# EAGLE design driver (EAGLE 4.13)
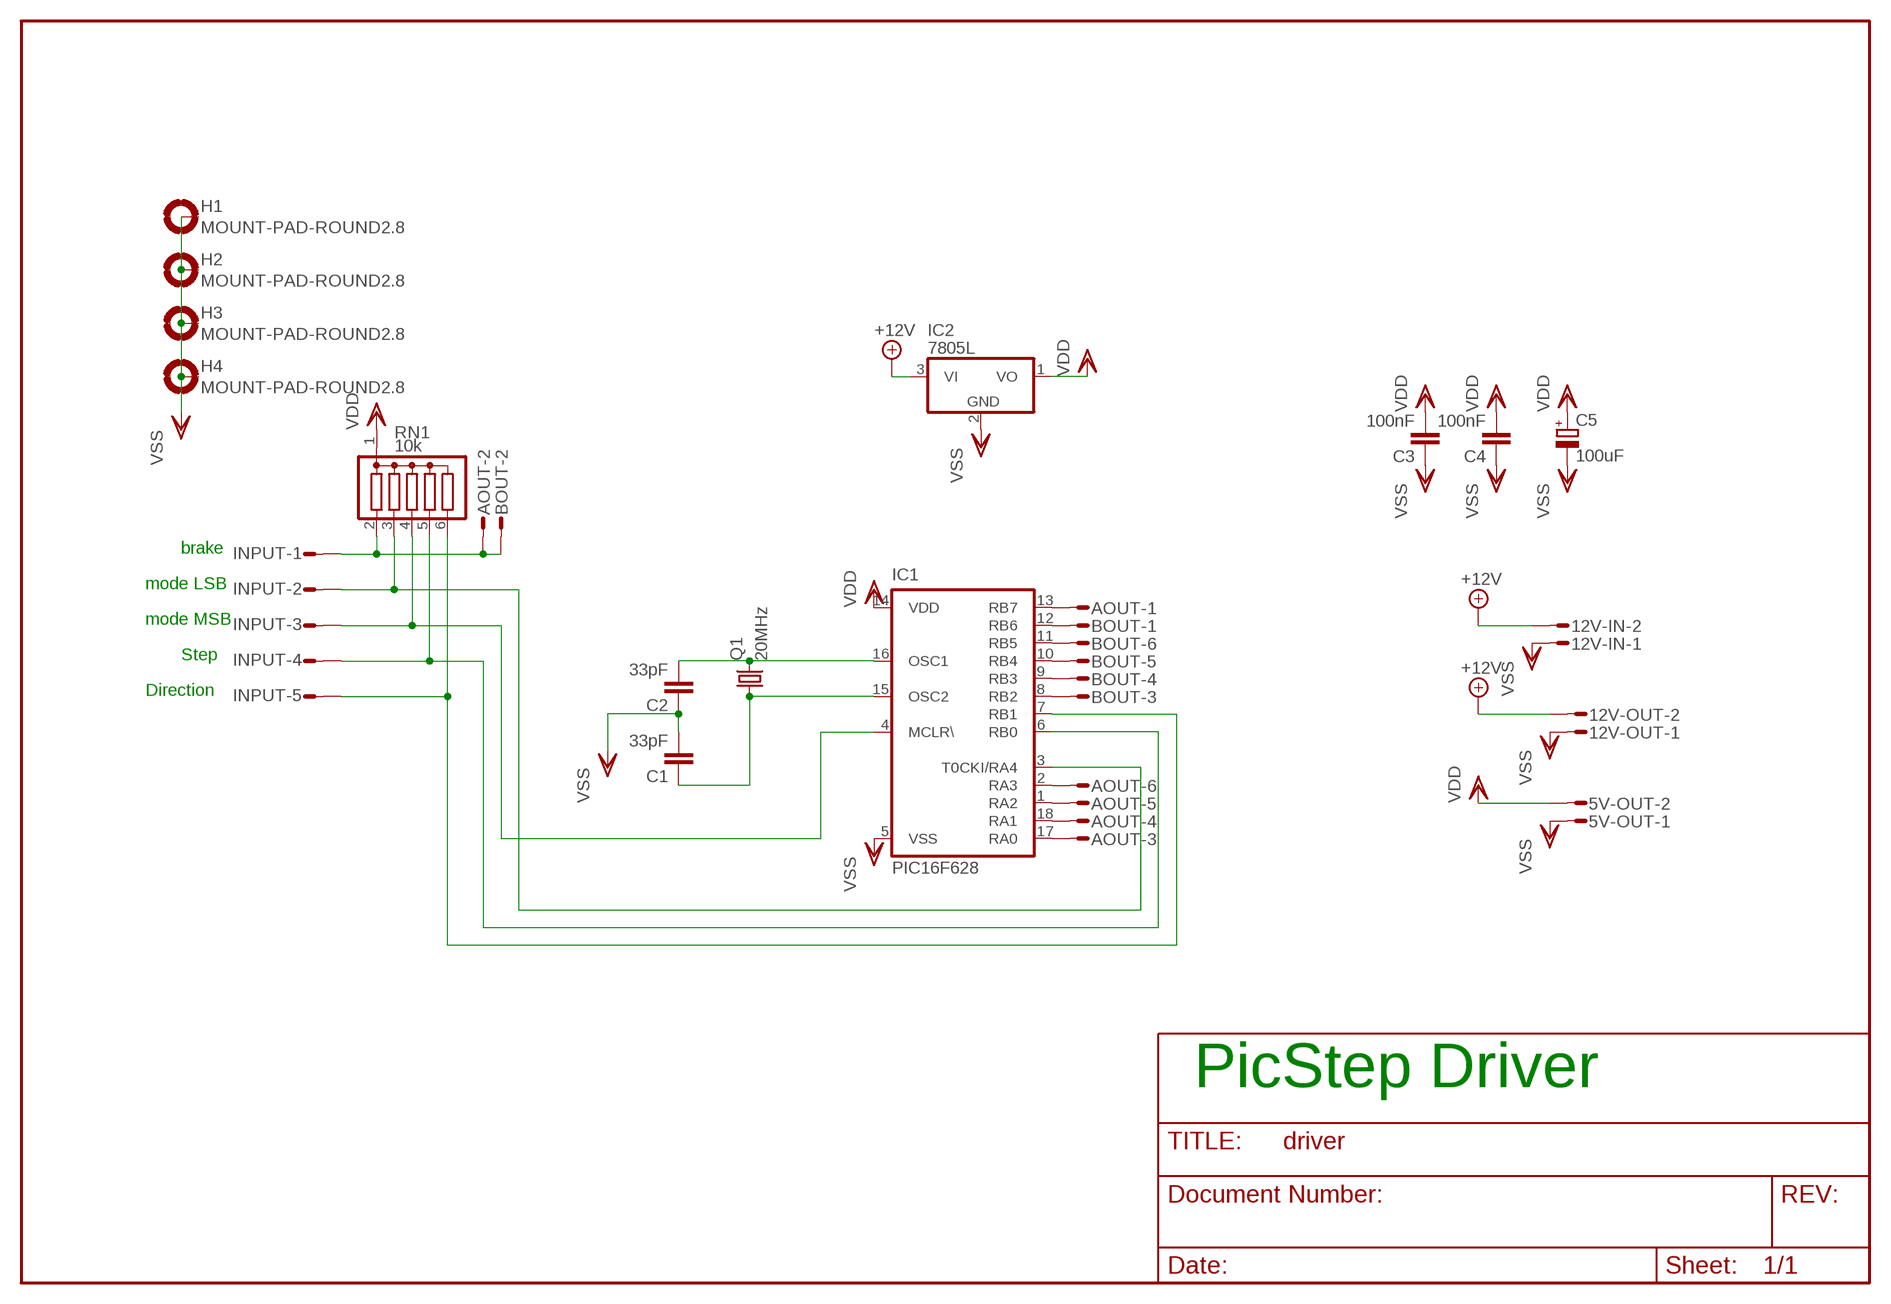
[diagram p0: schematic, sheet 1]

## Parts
5V-OUT  S02P  [S02P]
12V-IN  S02P  [S02P]
12V-OUT  S02P  [S02P]
AOUT  S06P  [S06P]
BOUT  S06P  [S06P]
C1  33pF  C-EU050-030X075  [C050-030X075]
C2  33pF  C-EU050-030X075  [C050-030X075]
C3  100nF  C-EU050-030X075  [C050-030X075]
C4  100nF  C-EU050-030X075  [C050-030X075]
C5  100uF  CPOL-EUE5-10.5  [E5-10,5]
H1  MOUNT-PAD-ROUND2.8  [2,8-PAD]
H2  MOUNT-PAD-ROUND2.8  [2,8-PAD]
H3  MOUNT-PAD-ROUND2.8  [2,8-PAD]
H4  MOUNT-PAD-ROUND2.8  [2,8-PAD]
IC1  PIC16F628  PIC16F84AP  [DIL18]
IC2  7805L  [TO92]
INPUT  S05P  [S05P]
Q1  20MHz  CRYTALHC49U-V  [HC49U-V]
RN1  10k  G05R  [SIL6]

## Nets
+12V: 12V-IN.2 12V-OUT.2 IC2.3(VI)
N$1: C2.2 IC1.16(OSC1) Q1.2
N$2: C1.1 IC1.15(OSC2) Q1.1
N$3: AOUT.2 BOUT.2 INPUT.1 RN1.2
N$4: IC1.3(T0CKI/RA4) INPUT.2 RN1.3
N$5: IC1.4(MCLR\) INPUT.3 RN1.4
N$6: IC1.6(RB0) INPUT.4 RN1.5
N$7: IC1.7(RB1) INPUT.5 RN1.6
N$8: AOUT.1 IC1.13(RB7)
N$9: AOUT.3 IC1.17(RA0)
N$10: AOUT.4 IC1.18(RA1)
N$11: AOUT.5 IC1.1(RA2)
N$12: AOUT.6 IC1.2(RA3)
N$13: BOUT.1 IC1.12(RB6)
N$14: BOUT.3 IC1.8(RB2)
N$15: BOUT.4 IC1.9(RB3)
N$16: BOUT.5 IC1.10(RB4)
N$17: BOUT.6 IC1.11(RB5)
VDD: 5V-OUT.2 C3.2 C4.2 C5.+ IC1.14(VDD) IC2.1(VO) RN1.1
VSS: 5V-OUT.1 12V-IN.1 12V-OUT.1 C1.2 C2.1 C3.1 C4.1 C5.- H1.B2,8(MOUNT) H2.B2,8(MOUNT) H3.B2,8(MOUNT) H4.B2,8(MOUNT) IC1.5(VSS) IC2.2(GND)

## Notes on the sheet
- brake
- mode LSB
- mode MSB
- Step
- Direction
- PicStep Driver

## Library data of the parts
5V-OUT 12V-IN 12V-OUT = con-amp-mt:S02P: AMP MT CONNECTOR
AOUT BOUT = con-amp-mt:S06P: AMP MT CONNECTOR
C1-C4 = rcl:C-EU: CAPACITOR, European symbol
C5 = rcl:CPOL-EU: POLARIZED CAPACITOR, European symbol
H1-H4 = holes:MOUNT-PAD-ROUND: MOUNTING PAD, round
IC1 = microchip:PIC16F8*: MICROCONTROLLER 8-Bit PIC16F8X Family - CMOS Flash/EEPROM Pin Compatible : PIC16F83, PIC16CR83, PIC16F84A, PIC16CR84 see also PIC16C*
IC2 = linear:78*: Positive VOLTAGE REGULATOR
INPUT = con-amp-mt:S05P: AMP MT CONNECTOR
Q1 = crystal:CRYTAL: CRYSTAL
RN1 = resistor-sil:G05R: SIL RESISTOR

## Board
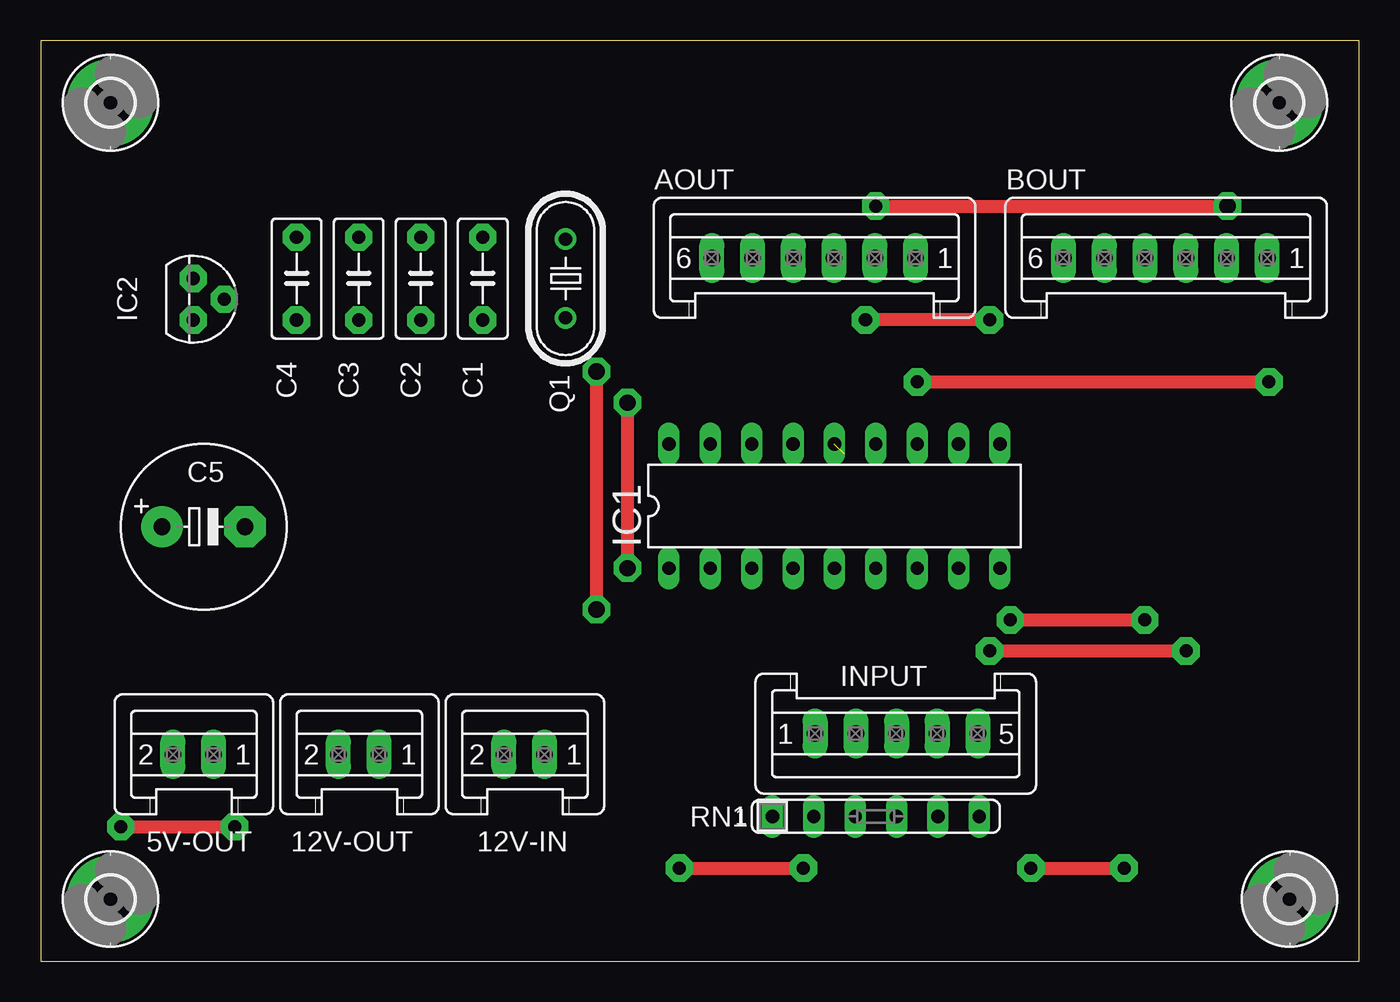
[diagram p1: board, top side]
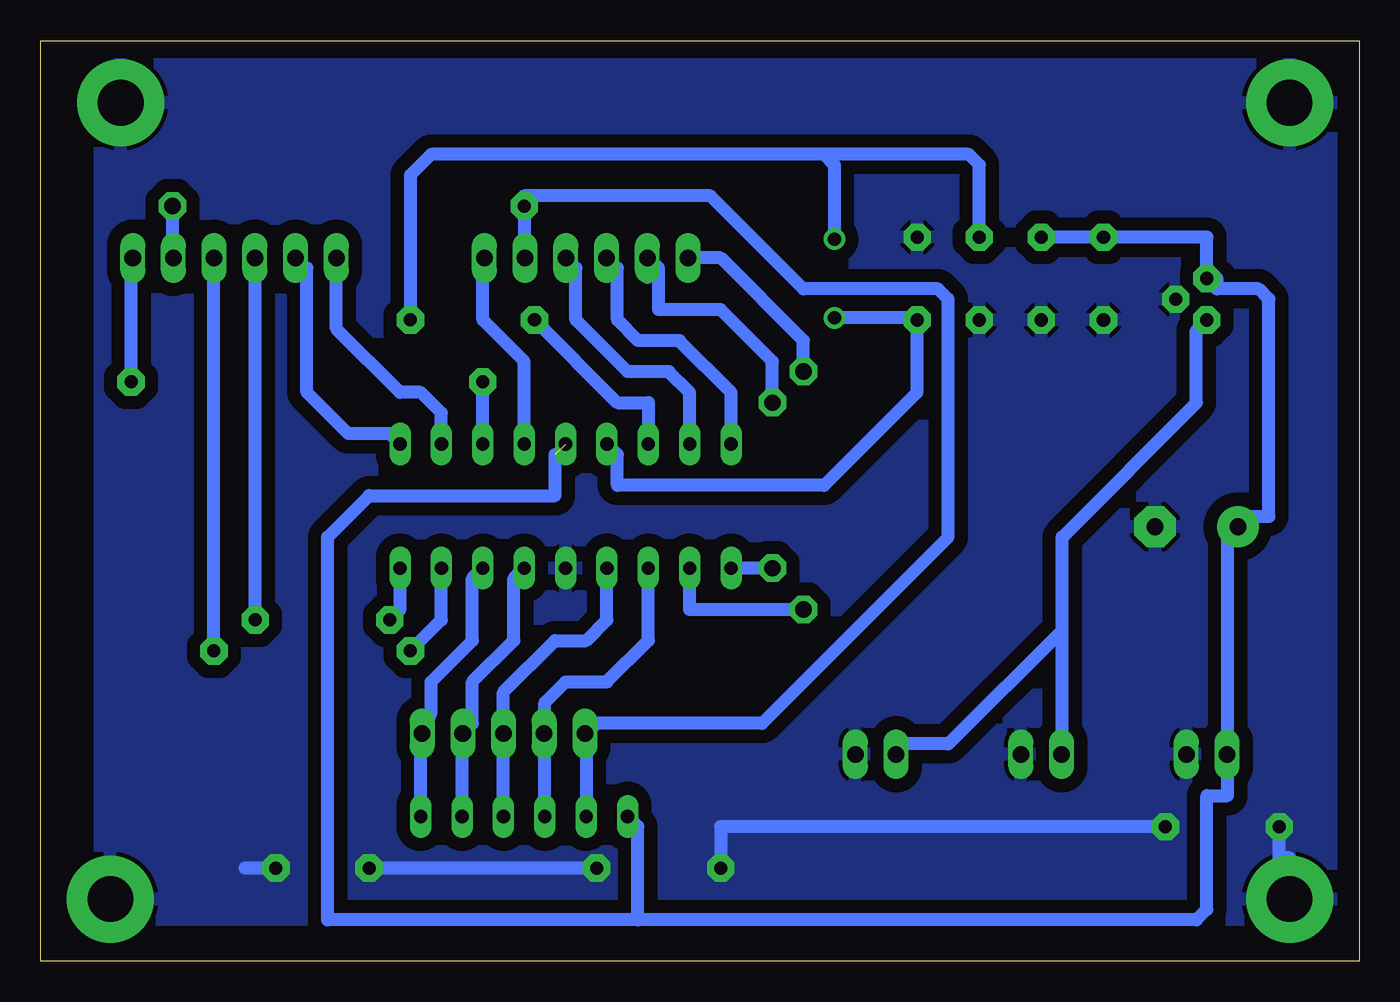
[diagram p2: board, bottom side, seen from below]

Size 80.95 x 56.5 mm. Coordinates in mm from the lower left corner, seen from the top.
Outline: 0,0 80.95,0 80.95,56.5 0,56.5 0,0
Copper layers (1*16): Top 0.035mm / dielectric 1.5mm / Bottom 0.035mm
Design rules "default": minimum track width 32mil, minimum drill 0.8mm, track to track 24mil, track to pad 24mil, pad to pad 8mil, via to via 8mil, smd to smd 8mil, copper to edge 40mil, drill to drill 8mil, minimum pad ring 10mil, minimum via ring 8mil, stop-mask expansion 4mil, vias tented up to drill 0mil, thermal gap 10mil

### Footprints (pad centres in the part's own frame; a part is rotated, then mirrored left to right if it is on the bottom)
S02P = drill 1.016 long: 1 1.25,0; 2 -1.25,0
S06P = drill 1.016 long: 1 6.25,0; 2 3.75,0; 3 1.25,0; 4 -1.25,0; 5 -3.75,0; 6 -6.25,0
C050-030X075 = drill 0.813 pad 1.676 octagon: 1 -2.54,0; 2 2.54,0
E5-10,5 = drill 1.016 pad 2.54 round: + -2.54,0 | drill 1.016 pad 2.54 octagon: - 2.54,0
2,8-PAD = drill 2.8 pad 5.334 round: B2,8 0,0
DIL18 = drill 0.813 long: 1 -10.16,-3.81; 2 -7.62,-3.81; 3 -5.08,-3.81; 4 -2.54,-3.81; 5 0,-3.81; 6 2.54,-3.81; 7 5.08,-3.81; 8 7.62,-3.81; 9 10.16,-3.81; 10 10.16,3.81; 11 7.62,3.81; 12 5.08,3.81; 13 2.54,3.81; 14 0,3.81; 15 -2.54,3.81; 16 -5.08,3.81; 17 -7.62,3.81; 18 -10.16,3.81
TO92 = drill 0.813 pad 1.676 octagon: 1 -1.27,0; 2 0,1.905; 3 1.27,0
S05P = drill 1.016 long: 1 5,0; 2 2.5,0; 3 0,0; 4 -2.5,0; 5 -5,0
HC49U-V = drill 0.813 round: 1 -2.413,0; 2 2.413,0
SIL6 = drill 0.813 long: 1 -6.35,0; 2 -3.81,0; 3 -1.27,0; 4 1.27,0; 5 3.81,0; 6 6.35,0

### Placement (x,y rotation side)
5V-OUT  9.36,12.7 0 top
12V-IN  29.68,12.7 0 top
12V-OUT  19.52,12.7 0 top
AOUT  47.46,43.17 0 top
BOUT  69.05,43.17 0 top
C1  27.14,41.91 90 top
C2  23.33,41.91 90 top
C3  19.52,41.91 90 top
C4  15.71,41.91 90 top
C5  10,26.66 0 top
H1  4.28,52.7 0 top
H2  4.28,3.8 0 top
H3  76.67,3.8 0 top
H4  76.03,52.7 0 top
IC1  48.73,27.94 0 top
IC2  9.36,40.63 270 top
INPUT  52.54,13.96 180 top
Q1  32.22,41.91 90 top
RN1  51.27,8.89 0 top

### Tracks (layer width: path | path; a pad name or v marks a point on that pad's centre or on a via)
+12V
  Bottom 0.813: 18.25,20.32 18.25,13.96 12V-OUT.2 | 18.25,20.32 18.25,26.03 10,34.28 10,38.73 IC2.3 | 18.25,20.32 25.23,13.33 27.77,13.33 12V-IN.2
N$1  (via drill 0.8 pad 1.68)
  Top 0.813: v58.26,39.37 v50.64,39.37
  Bottom 0.813: Q1.2 32.22,48.89 32.85,49.52 | 32.85,49.52 56.98,49.52 58.26,48.26 v58.26,39.37 | v50.64,39.37 45.55,34.28 43.65,34.28 IC1.16 | C2.2 23.33,48.89 23.96,49.52 32.85,49.52
N$2
  Bottom 0.813: IC1.15 45.55,31.11 45.55,29.2 32.85,29.2 27.14,34.92 C1.1 27.27,39.49 Q1.1
N$3  (via drill 0.8 pad 1.68, 1 pad 1.68)
  Top 0.813: v51.27,46.35 v72.86,46.35
  Bottom 0.813: BOUT.2 72.86,43.17 v72.86,46.35 | RN1.2 47.46,13.96 INPUT.1 46.83,14.6 36.66,14.6 25.23,26.03 25.23,40.63 25.87,41.27 34.12,41.27 39.84,46.98 51.27,46.98 v51.27,46.35 51.27,43.17 AOUT.2
N$4
  Bottom 0.813: IC1.3 43.65,19.68 46.19,17.14 48.73,17.14 50,15.87 INPUT.2 50,13.96 RN1.3
N$5
  Bottom 0.813: IC1.4 46.19,20.95 47.46,19.68 49.37,19.68 52.54,16.5 INPUT.3 RN1.4
N$6
  Bottom 0.813: IC1.6 51.91,23.49 51.91,19.68 54.45,17.14 54.45,14.6 INPUT.4 55.08,13.96 RN1.5
N$7
  Bottom 0.813: IC1.7 54.45,23.49 54.45,19.68 56.98,17.14 56.98,15.23 INPUT.5 57.62,13.96 RN1.6
N$8
  Bottom 0.813: IC1.13 51.27,36.83 53.81,39.37 53.81,41.91 AOUT.1
N$9
  Bottom 0.813: IC1.17 41.11,34.92 42.38,36.19 44.92,36.19 48.09,39.37 48.09,42.54 AOUT.3
N$10
  Bottom 0.813: IC1.18 38.57,34.92 41.75,38.09 44.29,38.09 45.55,39.37 45.55,42.54 AOUT.4
N$11  (via drill 1 pad 1.68)
  Top 0.813: v36.03,24.12 v36.03,34.28
  Bottom 0.813: 43.71,41.97 AOUT.5 43.02,42.54 43.02,40 39.21,40 36.03,36.83 v36.03,34.28 | v36.03,24.12 IC1.1
N$12  (via drill 1 pad 1.68)
  Top 0.813: v34.12,21.59 v34.12,36.19
  Bottom 0.813: v34.12,21.59 41.11,21.59 IC1.2 | v34.12,36.19 34.12,38.09 39.21,43.17 AOUT.6
N$13  (via drill 0.8 pad 1.68)
  Top 0.813: v53.81,35.55 v75.4,35.55
  Bottom 0.813: IC1.12 v53.81,35.55 | BOUT.1 75.4,43.17 v75.4,35.55
N$14  (via drill 0.8 pad 1.68)
  Top 0.813: v58.26,19.05 v70.32,19.05
  Bottom 0.813: IC1.8 56.35,20.95 v58.26,19.05 | BOUT.3 70.32,43.17 v70.32,19.05
N$15  (via drill 0.8 pad 1.68)
  Top 0.813: v59.52,20.95 v67.78,20.95
  Bottom 0.813: IC1.9 58.89,21.59 v59.52,20.95 | BOUT.4 67.78,43.17 v67.78,20.95
N$16
  Bottom 0.813: IC1.10 59.52,32.38 62.07,32.38 64.61,34.92 64.61,42.54 BOUT.5
N$17
  Bottom 0.813: BOUT.6 62.8,38.83 58.89,34.92 57.62,34.92 56.35,33.65 IC1.11
VDD  (1 unrouted)
  Bottom 0.813: 44.29,2.54 44.29,8.25 RN1.1 | 44.29,2.54 10,2.54 9.36,3.17 9.36,10.16 8.09,10.16 8.09,11.43 5V-OUT.2 8.09,13.96 8.09,26.03 C5.+ 6.82,27.3 5.55,27.3 5.55,40.63 6.19,41.27 8.72,41.27 8.72,41.91 IC2.1 9.36,44.45 C4.2 C3.2 | 49.37,31.11 49.37,28.57 60.8,28.57 63.34,26.03 63.34,2.54 44.29,2.54
VSS  (via drill 0.8 pad 1.68)
  Top 0.813: v4.92,8.25 v11.9,8.25 | v39.21,5.71 v46.83,5.71 | v60.8,5.71 v66.51,5.71
  Bottom 0.813: H2.B2,8 4.28,6.35 4.92,6.35 v4.92,8.25 | v11.9,8.25 39.21,8.25 v39.21,5.71 | v46.83,5.71 v60.8,5.71 | v66.51,5.71 68.41,5.71
  pour Bottom (isolate 0.813): 1.74,55.24 1.74,2.54 77.3,2.54 77.3,55.24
